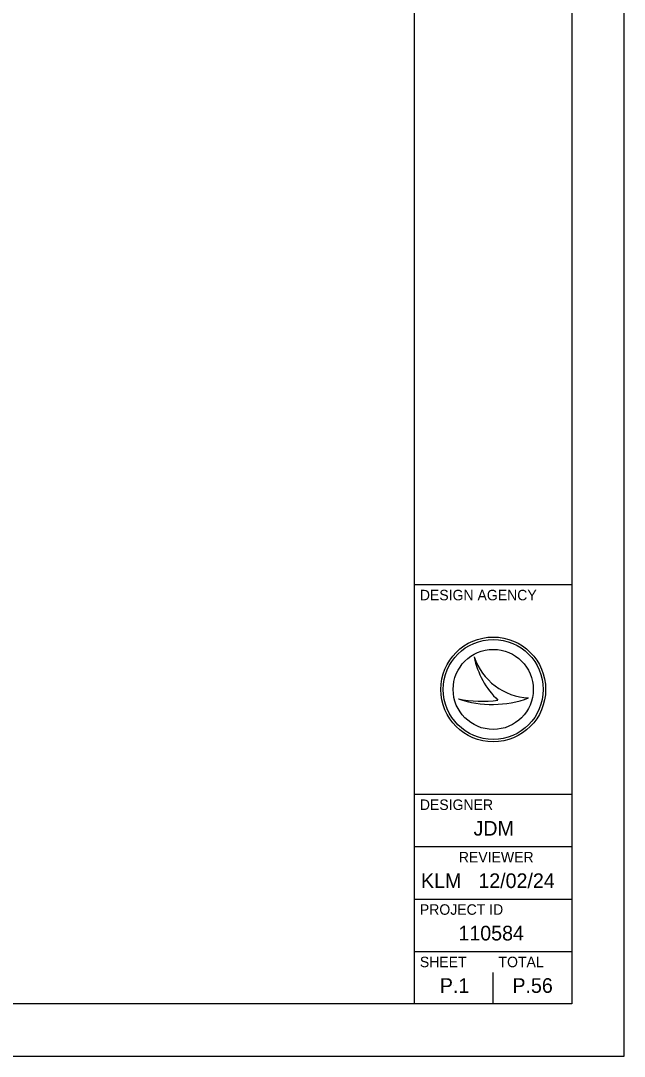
# Model space of a CAD drawing. Extents: x 0 to 34, y -1.6 to 22.
# Drawn here: x 28.24 to 34, y 0 to 9.88 of the extents above; entities that cross this region are included whole.
import ezdxf

# ---------------------------------------------------------------- set-up
doc = ezdxf.new("R2010")
doc.units = 0
for name, color, linetype in [('SH_Border', 7, 'Continuous'), ('SH_Cut_Line', 7, 'Continuous'), ('SH_Data', 7, 'Continuous')]:
    doc.layers.add(name, color=color, linetype=linetype)

msp = doc.modelspace()

# ---------------------------------------------------------------- linework, layer by layer
at = {"layer": 'SH_Border'}
for p, q in [((32, 0.5), (32, 21.5)), ((32, 4.5), (33.5, 4.5)), ((32, 2.5), (33.5, 2.5)), ((32, 2), (33.5, 2)), ((32, 1.5), (33.5, 1.5)), ((32, 1), (33.5, 1))]:
    msp.add_line(p, q, dxfattribs=at)
msp.add_lwpolyline([(1.5, 21.5), (33.5, 21.5), (33.5, 0.5), (1.5, 0.5)], close=True, dxfattribs=at)
at = {"layer": 'SH_Cut_Line'}
msp.add_lwpolyline([(0, 0), (34, 0), (34, 22), (0, 22)], close=True, dxfattribs=at)
at = {"layer": 'SH_Data'}
for p, q in [((32.5674, 3.8096), (32.5675, 3.8096)), ((32.75, 3.5), (32.75, 3.5)), ((32.4172, 3.4095), (32.4172, 3.4095)), ((33.0873, 3.4185), (33.0873, 3.4185)), ((32.75, 0.5), (32.75, 0.8)), ((32.375, 0.675), (32.375, 0.675))]:
    msp.add_line(p, q, dxfattribs=at)
for radius in [0.5, 0.4768, 0.4768, 0.3822]:
    msp.add_circle((32.75, 3.5), radius, dxfattribs=at)
for centre, radius, start, end in [((33.1159, 3.9976), 0.5798, 198.92567, 198.93195), ((33.3467, 3.9701), 0.7956, 191.63793, 191.64215), ((33.1159, 3.9976), 0.5798, 198.93195, 267.16574), ((33.3467, 3.9701), 0.7956, 191.64215, 226.09467), ((32.7394, 4.37), 1.0131, 251.45764, 290.08324), ((32.648, 4.6543), 1.2661, 259.49639, 259.49952), ((32.7394, 4.37), 1.0131, 251.45274, 251.45764), ((32.648, 4.6543), 1.2661, 259.49952, 276.66723)]:
    msp.add_arc(centre, radius, start, end, dxfattribs=at)

# ---------------------------------------------------------------- texts
for s, height, p in [('DESIGN AGENCY', 0.1, (32.05, 4.35)), ('DESIGNER', 0.1, (32.05, 2.35)), ('JDM', 0.14, (32.562, 2.105)), ('REVIEWER', 0.1, (32.4218, 1.85)), ('KLM', 0.14, (32.0613, 1.605)), ('12/02/24', 0.14, (32.6078, 1.605)), ('PROJECT ID', 0.1, (32.05, 1.35)), ('110584', 0.14, (32.4179, 1.105)), ('SHEET', 0.1, (32.05, 0.85)), ('TOTAL', 0.1, (32.8, 0.85)), ('P.1', 0.14, (32.2403, 0.605)), ('P.56', 0.14, (32.9327, 0.605))]:
    msp.add_text(s, height=height, dxfattribs=at).set_placement(p)

doc.saveas('drawing.dxf')
